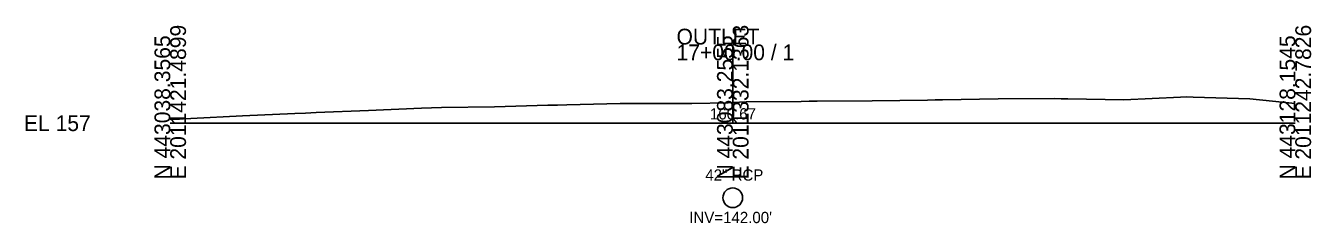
# Model space of a CAD drawing. Extents: x -26 to 1203, y -15 to 9526.
# Drawn here: x -25.7 to 202.8, y 6982.2 to 7017.3 of the extents above; entities that cross this region are included whole.
import ezdxf

# ---------------------------------------------------------------- set-up
doc = ezdxf.new("R2010")
doc.units = 0
for name, color, linetype in [('Exist Cross Section Cell', 7, 'Continuous'), ('Exist XS Center Line Elevation Label', 7, 'Continuous'), ('Exist XS Ground Line', 7, 'Continuous'), ('Prop XSC Text', 7, 'Continuous')]:
    doc.layers.add(name, color=color, linetype=linetype)

msp = doc.modelspace()

# ---------------------------------------------------------------- linework, layer by layer
at = {"layer": 'Exist Cross Section Cell'}
for p, q in [((100, 7000), (100, 7013.99)), ((0, 7000), (100, 7000)), ((100, 7000), (200, 7000))]:
    msp.add_line(p, q, dxfattribs=at)
at = {"layer": 'Exist XS Ground Line'}
msp.add_lwpolyline([(0, 7000.67), (1.67, 7000.75), (2.33, 7000.76), (3.66, 7000.83), (12.86, 7001.31), (22.15, 7001.72), (24.05, 7001.81), (25.93, 7001.88), (35.24, 7002.26), (44.64, 7002.65), (46.43, 7002.73), (48.2, 7002.77), (57.62, 7002.92), (67.14, 7003.18), (68.82, 7003.21), (70.48, 7003.27), (80.01, 7003.49), (89.63, 7003.51), (91.2, 7003.52), (92.75, 7003.52), (99.17, 7003.63), (100, 7003.67), (102.39, 7003.79), (112.13, 7003.86), (113.58, 7003.92), (115.02, 7003.92), (124.77, 7003.97), (134.62, 7004.11), (135.97, 7004.13), (137.29, 7004.15), (147.16, 7004.36), (157.12, 7004.37), (158.35, 7004.36), (159.57, 7004.32), (169.54, 7004.15), (179.61, 7004.6), (180.73, 7004.66), (181.84, 7004.63), (191.92, 7004.31), (200, 7003.53)], dxfattribs=at)
at = {"layer": 'Prop XSC Text'}
msp.add_circle((100, 6986.75), 1.75, dxfattribs=at)

# ---------------------------------------------------------------- texts
at = {"layer": 'Exist Cross Section Cell'}
for s, p in [('E 2011421.4899', (2.8, 6990)), ('E 2011332.1363', (102.8, 6990)), ('E 2011242.7826', (202.8, 6990)), ('N 443038.3565', (0, 6990)), ('N 443083.2555', (100, 6990)), ('N 443128.1545', (200, 6990))]:
    msp.add_text(s, height=2.8, rotation=90, dxfattribs=at).set_placement(p)
for s, p in [('OUTLET', (90, 7013.99)), ('17+00.00 / 1', (90, 7011.19)), ('EL 157', (-26, 6998.6))]:
    msp.add_text(s, height=2.8, dxfattribs=at).set_placement(p)
at = {"layer": 'Exist XS Center Line Elevation Label'}
msp.add_text('160.67', height=2, dxfattribs=at).set_placement((95.94, 7000.67))
at = {"layer": 'Prop XSC Text'}
for s, p in [('42" RCP', (95.12, 6989.8)), ("INV=142.00'", (92.26, 6982.26))]:
    msp.add_text(s, height=2, dxfattribs=at).set_placement(p)

doc.saveas('drawing.dxf')
